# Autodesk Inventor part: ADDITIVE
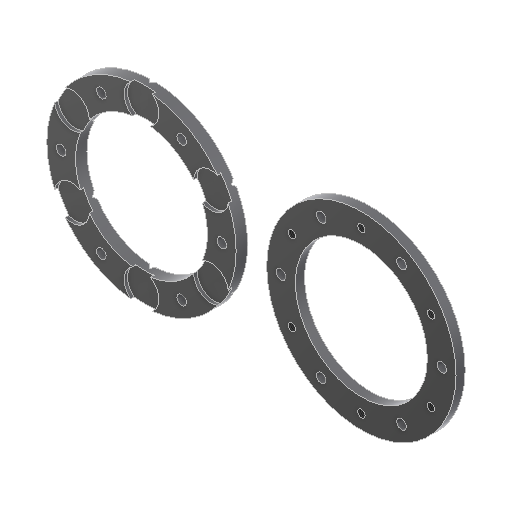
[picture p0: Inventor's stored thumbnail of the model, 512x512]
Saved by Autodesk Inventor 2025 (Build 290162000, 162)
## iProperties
Created: 2025-01
Part Number: ADDITIVE
Material: Thermoplastic Resin
Document SubType Name: Modeling
Designer: dansp
Density: 1.28 g/cm^3
Appearance: Smooth - Black
Mass: 15.0278 g
Surface Area: 81.5062 cm^2
Volume: 11.7404 cm^3
Author: dansp
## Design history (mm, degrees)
sketch "Sketch1"
  geometry: L1 (0, 57.75)-(0, -57.75) reference; L2 (-57.75, 0)-(57.75, 0) reference; C1 r 41.25 at (0, 0); C2 r 28.75 at (0, 0); 1 further point
  constraints: 2 centre point, 2 coincident
  dimensions: "d0" = 82.5 diameter of C1; "d1" = 12.5 radial gap between concentric circles of C1 C2
extrude "Extrusion1" new body sketch "Sketch1" distance "d2" = 5; taper "d3" = 0 deg
sketch "Sketch3" dims "d41" = 70 (= 0.5 x d40 + 0.5 x d39)
  geometry: C1 r 41.25 at (0, 0) reference; C2 r 28.75 at (0, 0) reference; C3 r 7.6 at (0, 35); 1 further point
  constraints: 2 vertical alignment, 1 centre point, 1 coincident, 2 other
  dimensions: "d39" = 82.5 diameter of C1 (derived); "d40" = 57.5 diameter of C2 (derived); "d42" = 15.2 diameter of C3
extrude "Extrusion3" cut sketch "Sketch3" distance "d16" = 1.5; taper "d17" = 0 deg
pattern_circular "Circular Pattern3" dims angle "d19" = 360 deg
sketch "Sketch5"
  geometry: L1 (-40.25, 0)-(40.25, 0) reference; L2 (0, -0.3)-(0, 1.8) reference; L3 (1.5, 0)-(0, 1.5); L4 (0, 1.5)-(-1.5, 0); L5 (-28.75, 0)-(28.75, 0) reference; 2 further points
  constraints: 4 end point, 3 point on line, 1 other
  dimensions: "d29" = 90 deg angle of L4 L3; "d30" = 1.5 distance from line of L3.end L1
extrude "Extrusion5" cut sketch "Sketch5" extent not by distance; stored distance "d31" = 0; taper "d32" = 0 deg
pattern_circular "Circular Pattern5" dims angle "d34" = 360 deg
sketch "Sketch8"
  geometry: L1 (-57.75, 0)-(57.75, 0) reference; L2 (0, -57.75)-(0, 57.75) reference; C1 r 2.1 at (35, 0); C2 r 2.1 at (-35, 0); A1 r 28.75 centre (0, 0) between (3.91, 28.483) and (-3.91, 28.483) reference; A2 r 7.6 centre (0, 35) between (-4.687, 40.983) and (-3.91, 28.483) reference; A3 r 41.25 centre (0, 0) between (4.687, 40.983) and (-4.687, 40.983) reference; A4 r 7.6 centre (0, 35) between (3.91, 28.483) and (4.687, 40.983) reference; A5 r 35 centre (0, 0) between (0, 35) and (35, 0); 1 further point
  constraints: 3 centre point, 2 point on circle, 1 coincident, 1 point on line, 1 symmetric about line, 1 other
  dimensions: "d44" = 4.2 diameter of C1
extrude "Extrusion6" cut sketch "Sketch8" extent not by distance; stored distance "d45" = 0; taper "d46" = 0 deg
pattern_circular "Circular Pattern7" dims angle "d51" = 360 deg
sketch "Sketch9"
  geometry: L1 (0, 57.75)-(0, -57.75) reference; L2 (-57.75, 0)-(57.75, 0) reference; C1 r 41.25 at (94.818, 0); C2 r 28.75 at (94.818, 0); 1 further point
  constraints: 2 centre point, 1 coincident, 1 point on line
  dimensions: "d53" = 82.5 diameter of C1; "d54" = 12.5 radial gap between concentric circles of C1 C2
extrude "Extrusion7" join sketch "Sketch9" distance "d55" = 4; taper "d56" = 0 deg
sketch "Sketch10"
  geometry: L1 (0, 0)-(0, 47.452); C1 r 28.75 at (0, 0) reference; 6 further points
  constraints: 3 point on line, 2 end point, 2 vertical alignment, 1 vertical, 2 other
  dimensions: "d57" = 12.5 distance of point (0, 28.75) point (0, 41.25) (derived); "d58" = 6.25 distance of point (0, 28.75) point (0, 35) (= 0.5 x d57)
hole "Hole1" sketch "Sketch10" at (0, 35) diameter "d59" = 3.242; stored, may be unused: countersink angle "d63" = 90 deg, drill point angle "d65" = 118 deg; dims "d60" = 8, "d61" = 4, "d62" = 2, "d64" = 8
pattern_circular "Circular Pattern8" dims angle "d67" = 360 deg
sketch "Sketch11"
  geometry: L1 (-171.531, 0)-(76.714, 0) reference; C1 r 2.1 at (-35, 0); C2 r 1.621 at (30.311, 17.5) reference; C3 r 1.621 at (30.311, -17.5) reference; C4 r 1.621 at (0, -35) reference; C5 r 1.621 at (-30.311, -17.5) reference; C6 r 1.621 at (-30.311, 17.5) reference; C7 r 1.621 at (0, 35) reference; C8 r 41.25 at (0, 0) reference; C9 r 28.75 at (0, 0) reference; A1 r 35 centre (0, 0) between (-30.311, 17.5) and (-35, 0); 1 further point
  constraints: 2 centre point, 2 point on circle, 1 coincident, 1 point on line
  dimensions: "d69" = 4.2 diameter of C1
extrude "Extrusion8" cut sketch "Sketch11" extent not by distance; stored distance "d70" = 0; taper "d71" = 0 deg
pattern_circular "Circular Pattern9" dims angle "d73" = 360 deg
body "Solid1"
node "Projected Loop2"
node "Projected Loop6"
node "Projected Loop7"
node "Projected Loop8"
